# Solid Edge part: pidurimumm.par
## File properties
Title: pidurimumm
Author: Stella-Marii
Template: iso metric part.par
Last saved by: Stella-Marii
Revision: 5
Application: Solid Edge
Density: 1024,000 kg/m^3
Accuracy: 0,990
Username: Stella-Marii
Document Number: 30
Material: ABS Plastic, high impact
Face Style: Red
Fill Style: ANSI34(Plastic)
Virtual Style: Red (Shiny)
Grouping: Non-metals\Plastics
LibraryName: Materials
Coef. of Thermal Exp: 9e-05
Thermal Conductivity: 0.2
Specific Heat: 0.0
Modulus of Elasticity: 1378951400.0
Poisson's Ratio: 0.4
Yield Stress: 31026406.5
Ultimate Stress: 0.0
Elongation: 0.0
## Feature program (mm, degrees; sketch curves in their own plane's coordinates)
sketch for "unnamed RevolvedProtrusion 1" plane through (0, 0, 0) normal (0, 0, 1) x-axis (1, 0, 0)
  line (0, 5) -> (0, -5)
revolve "unnamed RevolvedProtrusion 1" add finite 360 deg
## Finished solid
Body 1: solid body, 1 face, 0 edges, 0 vertices.
  Faces by surface: sphere 1
Spherical faces by radius (mm): R5 x1
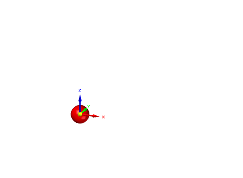
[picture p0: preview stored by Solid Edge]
